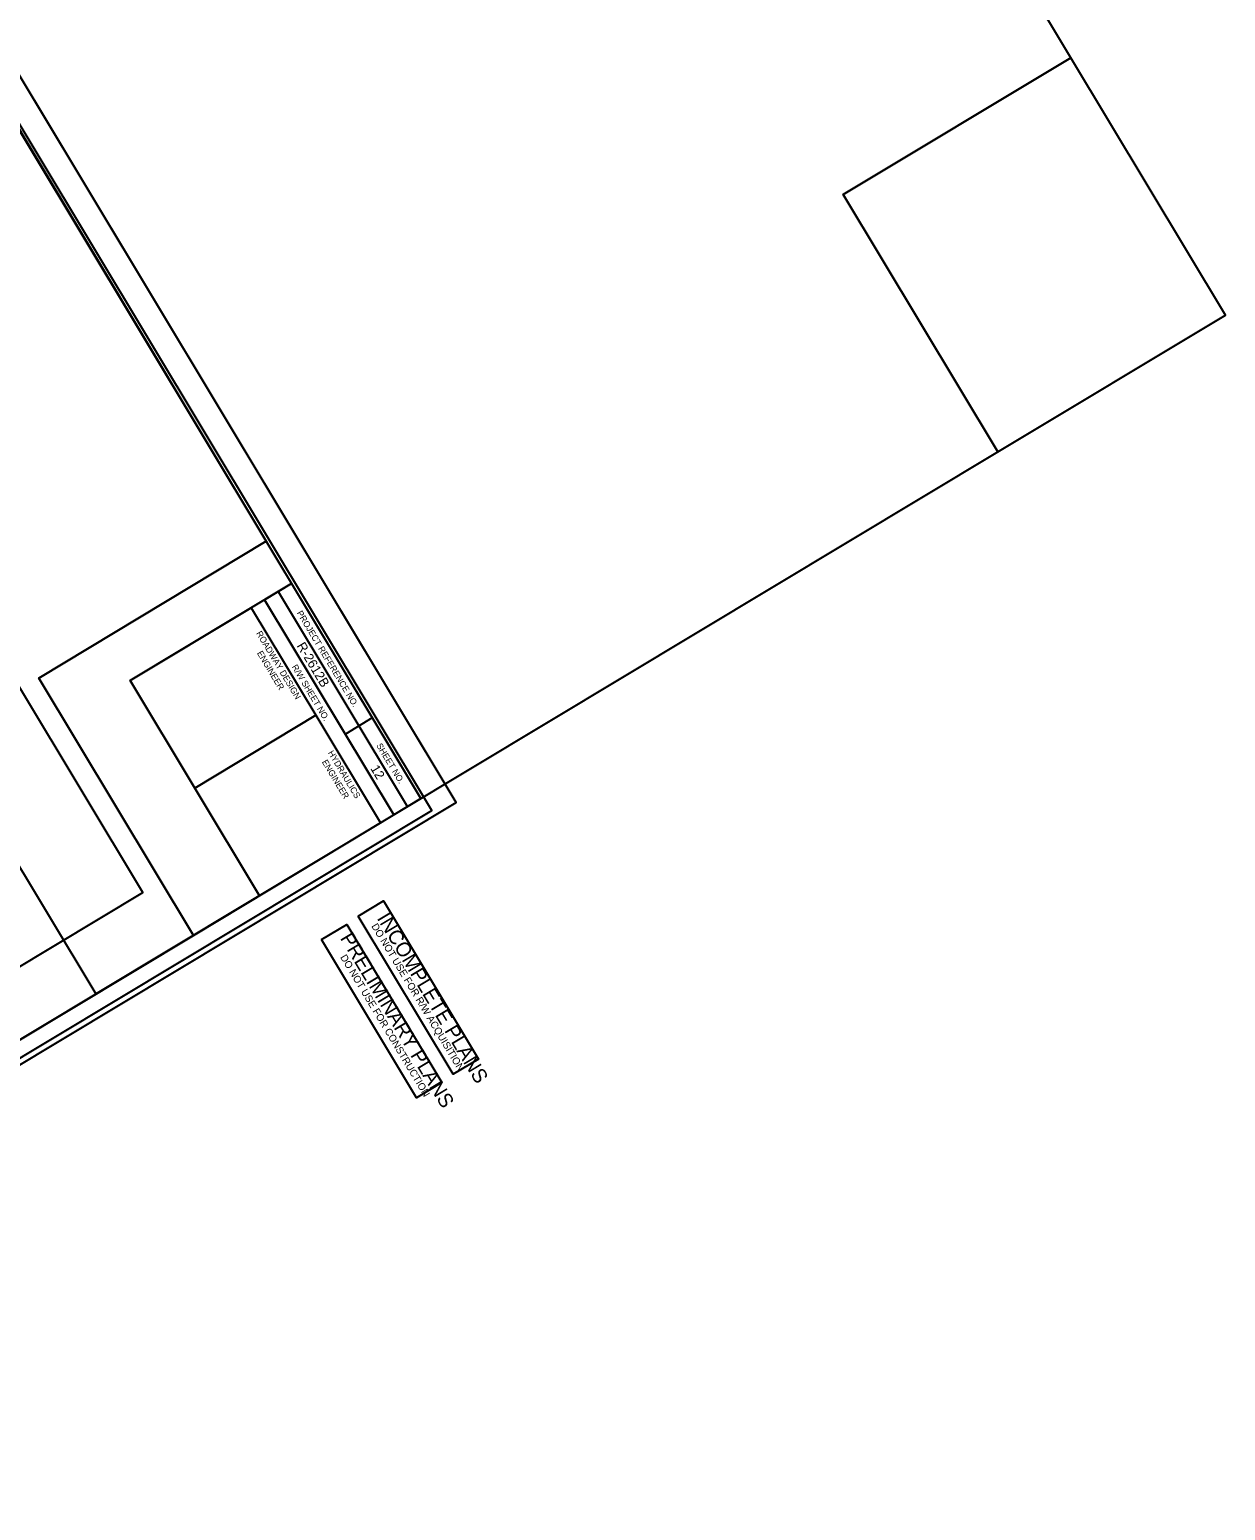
# Model space of a CAD drawing. Extents: x 1778994 to 1781413, y 814194 to 816432.
# Drawn here: x 1780460 to 1781413, y 814194 to 815374 of the extents above; entities that cross this region are included whole.
import ezdxf

# ---------------------------------------------------------------- set-up
doc = ezdxf.new("R2010")
doc.units = 0
for name, color, linetype in [('Sheet Clip Boundary CELL', 7, 'Continuous'), ('Sheet Cutting Line CELL', 7, 'Continuous'), ('Sheet Data Field CELL', 7, 'Continuous'), ('Sheet Layout Plan Border', 7, 'Continuous'), ('Sheet Plan CELL', 7, 'Continuous'), ('Sheet Plan Layout CELL', 7, 'Continuous'), ('Sheet Plot Border Inside CELL', 7, 'Continuous'), ('Sheet Plot Border Outside CELL', 7, 'Continuous'), ('Sheet Sticker Incomplete CELL', 7, 'Continuous'), ('Sheet Sticker Preliminary CELL', 7, 'Continuous')]:
    doc.layers.add(name, color=color, linetype=linetype)

msp = doc.modelspace()

# ---------------------------------------------------------------- linework, layer by layer
at = {"layer": 'Sheet Clip Boundary CELL'}
msp.add_lwpolyline([(1779124.7, 815463.4), (1779845.7, 814263.4), (1780549.9, 814686.5), (1780452.5, 814848.7), (1780452.5, 814848.7), (1779828.9, 815886.5)], close=True, dxfattribs=at)
at = {"layer": 'Sheet Cutting Line CELL'}
msp.add_line((1780799.5, 814758.3), (1779932.5, 816201.3), dxfattribs=at)
at = {"layer": 'Sheet Layout Plan Border'}
msp.add_lwpolyline([(1779124.7, 815463.4), (1779845.7, 814263.4), (1780549.9, 814686.5), (1780452.5, 814848.7), (1779828.9, 815886.5)], close=True, dxfattribs=at)
at = {"layer": 'Sheet Plan CELL'}
for p, q in [((1779998.9, 816047.1), (1780668.5, 814932.8)), ((1780668.5, 814932.8), (1780539.8, 814855.5)), ((1780647, 814919.8), (1780636.3, 814913.4)), ((1780647, 814919.8), (1780750, 814748.4)), ((1780647, 814919.8), (1780750, 814748.4)), ((1780657.7, 814926.3), (1780760.7, 814754.8)), ((1780539.8, 814855.5), (1780642.9, 814684)), ((1780687.8, 814827.7), (1780591.4, 814769.7)), ((1780732.8, 814825.6), (1780711.4, 814812.7)), ((1780642.9, 814684), (1779871.5, 814220.5))]:
    msp.add_line(p, q, dxfattribs=at)
for points in [[(1780771.5, 814761.3), (1779998.9, 816047), (1779098.9, 815506.3), (1779871.5, 814220.5)], [(1780668.5, 814932.8), (1780771.5, 814761.3), (1780750, 814748.4), (1780647, 814919.8)], [(1780636.3, 814913.4), (1780687.8, 814827.7), (1780591.3, 814769.7), (1780539.8, 814855.5)], [(1780687.8, 814827.7), (1780739.3, 814742), (1780642.9, 814684), (1780591.3, 814769.7)]]:
    msp.add_lwpolyline(points, close=True, dxfattribs=at)
at = {"layer": 'Sheet Plan Layout CELL'}
for points in [[(1780639.9, 816432.2), (1779739.9, 815891.4), (1780512.5, 814605.7), (1781231.2, 815037.5), (1781108, 815242.6), (1781289.3, 815351.5)], [(1779998.9, 816047.1), (1779098.9, 815506.3), (1779871.5, 814220.5), (1780590.2, 814652.4), (1780467, 814857.4), (1780648.3, 814966.4)], [(1781108, 815242.6), (1781231.2, 815037.5), (1781412.5, 815146.4), (1781289.3, 815351.5)], [(1780467, 814857.4), (1780590.2, 814652.4), (1780771.5, 814761.3), (1780648.3, 814966.4)]]:
    msp.add_lwpolyline(points, close=True, dxfattribs=at)
at = {"layer": 'Sheet Plot Border Inside CELL'}
msp.add_lwpolyline([(1779017.7, 815636.5), (1779875.8, 814208.5), (1780780.1, 814751.9), (1779922, 816179.9)], close=True, dxfattribs=at)
at = {"layer": 'Sheet Plot Border Outside CELL'}
msp.add_lwpolyline([(1778993.9, 815637.4), (1779860.9, 814194.3), (1780799.5, 814758.3), (1779932.5, 816201.3)], close=True, dxfattribs=at)
at = {"layer": 'Sheet Sticker Incomplete CELL'}
msp.add_lwpolyline([(1780721.5, 814667.8), (1780741.6, 814679.9), (1780817.3, 814553.9), (1780797.2, 814541.8)], close=True, dxfattribs=at)
at = {"layer": 'Sheet Sticker Preliminary CELL'}
msp.add_lwpolyline([(1780692.2, 814649), (1780712.4, 814661.1), (1780788.1, 814535.1), (1780767.9, 814523)], close=True, dxfattribs=at)

# ---------------------------------------------------------------- texts
at = {"layer": 'Sheet Data Field CELL'}
for s, p in [('R-2612B', (1780672.3, 814883.1)), ('12', (1780731, 814785.4))]:
    msp.add_text(s, height=7.5, rotation=301, dxfattribs=at).set_placement(p)
at = {"layer": 'Sheet Plan CELL'}
for s, p in [('PROJECT REFERENCE NO.', (1780672.4, 814909.2)), ('ROADWAY DESIGN', (1780640, 814893)), ('ENGINEER', (1780640.7, 814877.2)), ('R/W SHEET NO.', (1780668.4, 814866.3)), ('SHEET NO.', (1780735.8, 814803.6)), ('ENGINEER', (1780692.4, 814790.5)), ('HYDRAULICS', (1780697.2, 814797.8))]:
    msp.add_text(s, height=5, rotation=301, dxfattribs=at).set_placement(p)
at = {"layer": 'Sheet Sticker Incomplete CELL'}
for s, height, p in [('INCOMPLETE PLANS', 11.52, (1780736.1, 814666.1)), ('DO NOT USE FOR R/W ACQUISITION', 5.76, (1780731.8, 814659.8))]:
    msp.add_text(s, height=height, rotation=301, dxfattribs=at).set_placement(p)
at = {"layer": 'Sheet Sticker Preliminary CELL'}
for s, height, p in [('PRELIMINARY PLANS', 11.52, (1780706.8, 814650.2)), ('DO NOT USE FOR CONSTRUCTION', 5.76, (1780707, 814635))]:
    msp.add_text(s, height=height, rotation=301, dxfattribs=at).set_placement(p)

doc.saveas('drawing.dxf')
